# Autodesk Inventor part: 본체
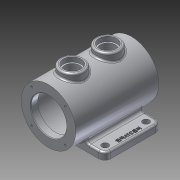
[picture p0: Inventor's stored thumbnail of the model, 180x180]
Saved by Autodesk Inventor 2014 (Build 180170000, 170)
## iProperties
Created: 2014-12
Part Number: 본체
Material: 알루미늄 6061
Document SubType Name: Modeling
Designer: Owner
Density: 2.71 g/cm^3
Appearance: 알루미늄 - 평지
Mass: 1293.91 g
Surface Area: 1040.14 cm^2
Volume: 477.456 cm^3
Author: Owner
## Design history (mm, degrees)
node "작업 평면1"
sketch "스케치2"
  geometry: C1 r 46 at (0, 0); 1 further point
  constraints: 1 centre point, 1 coincident
  dimensions: "d5" = 92 diameter of C1
extrude "돌출2" new body sketch "스케치2" stored distance "d6" = 140; taper "d7" = 0 deg
sketch "스케치3"
  geometry: C1 r 46 at (0, 0) reference; C2 r 30 at (0, 0)
  constraints: 1 centre point, 1 coincident
  dimensions: "d8" = 60 diameter of C2
extrude "돌출3" cut sketch "스케치3" distance "d9" = 12; taper "d10" = 0 deg
sketch "스케치4"
  geometry: C1 r 30 at (0, 0) reference; C2 r 37.5 at (0, 0)
  constraints: 1 centre point, 1 coincident
  dimensions: "d11" = 75 diameter of C2
extrude "돌출4" cut sketch "스케치4" distance "d12" = 70; taper "d13" = 0 deg
node "작업 평면2"
sketch "스케치5"
  geometry: L1 (-65, -40)-(65, -40); L2 (65, -40)-(65, 55); L3 (65, 55)-(-65, 55); L4 (-65, 55)-(-65, -40); L5 (46, 70)-(-46, 70) reference; L6 (-46, -70)-(46, -70) reference; 2 further points
  constraints: 8 end point, 2 parallel, 1 horizontal, 1 midpoint, 1 perpendicular, 1 vertical alignment
  dimensions: "d68" = 30 distance between parallel lines of L1 L6; "d69" = 95 distance of L3.end L1.start; "d70" = 130 distance of L2.end L3.end
extrude "돌출5" join sketch "스케치5" distance "d17" = 12; taper "d18" = 0 deg
node "작업 평면3"
sketch "스케치6"
  geometry: L1 (-25.923, -40)-(25.923, -40) reference; L2 (25.923, -40)-(25.923, 55) reference; L3 (25.923, 55)-(-25.923, 55) reference; L4 (-25.923, 55)-(-25.923, -40) reference; L5 (46, 70)-(-46, 70) reference; L6 (-46, -70)-(46, -70) reference; C1 r 20 at (0, 30); C2 r 20 at (0, -30); 1 further point
  constraints: 2 centre point, 2 vertical alignment
  dimensions: "d20" = 40 diameter of C1; "d21" = 40 diameter of C2; "d22" = 40 distance from line of C2.centre L6; "d23" = 60 distance of C1.centre C2.centre
extrude "돌출6" join sketch "스케치6" stored distance "d24" = 12; taper "d25" = 0 deg
sketch "스케치7"
  geometry: C1 r 20 at (0, 0) reference; C2 r 15 at (0, 0); C3 r 20 at (0, -60) reference; C4 r 15 at (0, -60); 1 further point
  constraints: 2 centre point, 2 coincident
  dimensions: "d26" = 30 diameter of C2; "d27" = 30 diameter of C4
extrude "돌출7" cut sketch "스케치7" distance "d28" = 8; taper "d29" = 0 deg
sketch "스케치8"
  geometry: C1 r 15 at (0, 0) reference; C2 r 12.5 at (0, 0); C3 r 12.5 at (0, -60); 2 further points
  constraints: 2 centre point, 1 coincident, 1 vertical alignment, 1 other
  dimensions: "d30" = 25 diameter of C2; "d32" = 25 diameter of C3; "d33" = 60 distance of C3.centre C1.centre
extrude "돌출8" cut sketch "스케치8" stored distance "d34" = 8; taper "d35" = 0 deg
sketch "스케치9"
  geometry: L1 (65, -40)-(65, 55) reference; L2 (65, 55)-(25.923, 55) reference; C1 r 5.5 at (52.5, 42); 1 further point
  constraints: 1 centre point
  dimensions: "d36" = 11 diameter of C1; "d37" = 12.5 distance from line of C1.centre L1; "d38" = 13 distance from line of C1.centre L2
extrude "돌출9" cut sketch "스케치9" stored distance "d39" = 8; taper "d40" = 0 deg
sketch "스케치10"
  geometry: L1 (1.801, 1.415)-(41.801, 1.415); L2 (0, 0)-(28.284, 28.284); L3 (0, 0)-(40, 0); C1 r 46 at (0, 0) reference; 1 further point
  constraints: 6 end point, 2 horizontal, 1 coincident, 1 equal length
  dimensions: "d43" = 40 distance of L2.start L2.end; "d44" = 45 deg angle of L3 L2
hole "구멍1" sketch "스케치10" at (28.284, 28.284) diameter "d45" = 3.242; stored, may be unused: countersink angle "d49" = 90 deg, drill point angle "d51" = 118 deg; dims "d46" = 8, "d47" = 4, "d48" = 2, "d50" = 10
fillet "모깎기1" dims "d59" = 5
fillet "모깎기2" dims "d60" = 10
fillet "모깎기3" dims "d61" = 3
fillet "모깎기4" dims "d62" = 3
fillet "모깎기5" dims "d63" = 3
chamfer "모따기1" distance "d64" = 1; stored, may be unused: second distance "d65" = 2, angle "d66" = 45 deg
fillet "모깎기6" dims "d67" = 3
sketch "스케치14"
  geometry: L1 (65, -30)-(65, 45) reference; L2 (38.884, -40)-(55, -40) reference; C1 r 5.5 at (52.5, -27); 1 further point
  constraints: 1 centre point
  dimensions: "d74" = 11 diameter of C1; "d75" = 12.5 distance from line of L1 C1.centre; "d76" = 13 distance from line of L2 C1.centre
extrude "돌출10" cut sketch "스케치14" stored distance "d77" = 0; taper "d78" = 0 deg
sketch "스케치15"
  geometry: L1 (65, -30)-(65, 45) reference; C1 r 5.5 at (52.5, -27) reference; 2 further points
  constraints: 1 other
  dimensions: "d79" = 35 vertical distance of point (57, 8) C1.centre; "d80" = 8 distance from line of L1 point (57, 8)
feature "엠보싱2" sketch "스케치15" dims "d81" = 1, "d82" = 0
node "솔리드2"
mirror "대칭1"
mirror "대칭3"
pattern_circular "원형 패턴1" dims angle "d53" = 360 deg
mirror "대칭4"
mirror "대칭5"
node "투영된 루프1"
node "투영된 루프2"
node "투영된 루프3"
other parameters: "d4" = 0, "d19" = 56
